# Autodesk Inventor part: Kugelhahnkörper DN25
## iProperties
Shininess: 64.0
Length Units: 11269
Angle Units: 11279
Time Units: 11290
Mass Units: 11283
Length Display Precision: 3
Angle Display Precision: 2
Compacted: True
Part Number: Kugelhahnkörper DN25
Document SubType Name: Modeling
Created: 2004-08
Material: Messing (weiches, gelbes Messing)
Designer: AG
Manufacturer: Standard
Standards Organization: Custom
Density: 0.0
Volumn: 0.0
Area: 0.0
PropertySet Name: Model Information
Control State: 0
Master: False
Checked Out: False
Author: AG
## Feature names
1. Extrusion1
2. Drehung1 [Revolution]
3. Drehung2 [Revolution]
4. Extrusion2
5. Runde Anordnung1 [Circular Pattern]
6. Extrusion3
7. Extrusion4
8. Extrusion5
9. Spiegeln1 [Mirror]
10. Bohrung1 [Hole]
11. Drehung3 [Revolution]
12. Bohrung2 [Hole]
13. Bohrung3 [Hole]
14. Bohrung4 [Hole]
